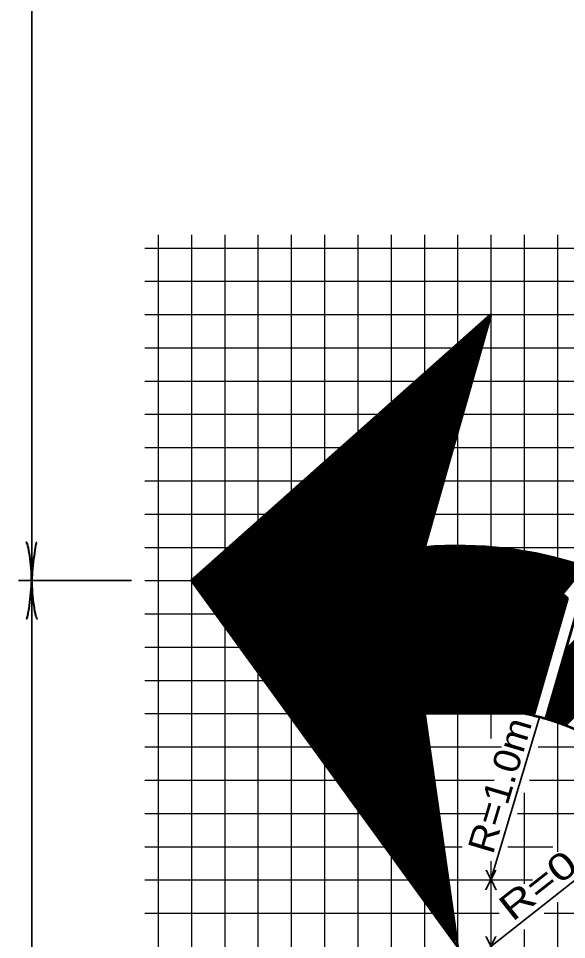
# Model space of a CAD drawing. Extents: x -96 to 617, y -65 to 388.
# Drawn here: x 111.1 to 152.3, y 261.1 to 330.4 of the extents above; entities that cross this region are included whole.
import ezdxf
from ezdxf.enums import TextEntityAlignment as Align

# ---------------------------------------------------------------- set-up
doc = ezdxf.new("R2010")
doc.units = 0
doc.layers.add('1', color=7, linetype='Continuous', lineweight=53)

msp = doc.modelspace()

# ---------------------------------------------------------------- linework, layer by layer
at = {"layer": '1', "lineweight": 25}
for p, q in [((121.579, 314.099), (121.579, 257.099)), ((124.079, 314.099), (124.079, 257.099)), ((126.579, 314.099), (126.579, 257.099)), ((129.079, 314.099), (129.079, 257.099)), ((131.579, 314.099), (131.579, 257.099)), ((134.079, 314.099), (134.079, 257.099)), ((136.579, 314.099), (136.579, 257.099)), ((139.079, 314.099), (139.079, 257.099)), ((141.579, 314.099), (141.579, 257.099)), ((144.079, 314.099), (144.079, 257.099)), ((146.579, 314.099), (146.579, 276.227)), ((149.079, 314.099), (149.079, 278.443)), ((151.579, 314.099), (151.579, 284.164)), ((120.579, 313.099), (182.579, 313.099)), ((120.579, 310.599), (182.579, 310.599)), ((120.579, 308.099), (182.579, 308.099)), ((120.579, 305.599), (154.079, 305.599)), ((120.579, 303.099), (182.579, 303.099)), ((120.579, 300.599), (182.579, 300.599)), ((120.579, 298.099), (182.579, 298.099)), ((120.579, 295.599), (182.579, 295.599)), ((120.579, 293.099), (182.579, 293.099)), ((120.579, 290.599), (141.579, 290.599)), ((142.756, 290.599), (182.579, 290.599)), ((120.579, 288.099), (124.079, 288.099)), ((124.079, 288.099), (152.781, 288.099)), ((120.579, 285.599), (151.995, 285.599)), ((120.579, 283.099), (151.269, 283.099)), ((120.579, 280.599), (150.543, 280.599)), ((151.547, 280.599), (182.579, 280.599)), ((120.579, 278.099), (141.579, 278.099)), ((149.079, 278.099), (149.817, 278.099)), ((150.821, 278.099), (182.579, 278.099)), ((120.579, 275.599), (147.368, 275.599)), ((150.135, 275.599), (182.579, 275.599)), ((120.579, 273.099), (146.831, 273.099)), ((149.469, 273.099), (182.579, 273.099)), ((149.079, 272.153), (149.079, 266.649)), ((120.579, 270.599), (146.16, 270.599)), ((120.579, 268.099), (144.415, 268.099)), ((147.841, 268.099), (151.244, 268.099)), ((146.579, 267.007), (146.579, 257.099)), ((149.079, 266.649), (149.079, 265.306)), ((120.579, 265.599), (146.579, 265.599)), ((146.579, 265.599), (149.695, 265.599)), ((151.579, 263.939), (151.579, 257.099)), ((120.579, 263.099), (147.189, 263.099)), ((150.578, 263.099), (164.079, 263.099)), ((149.079, 261.867), (149.079, 257.099))]:
    msp.add_line(p, q, dxfattribs=at)
at = {"layer": '1'}
for p, q in [((125.155, 286.619), (146.556, 308.02)), ((125.229, 286.516), (146.486, 307.772)), ((125.304, 286.414), (146.415, 307.525)), ((125.081, 286.721), (145.493, 307.134)), ((125.378, 286.312), (146.344, 307.277)), ((125.453, 286.209), (146.273, 307.03)), ((125.527, 286.107), (146.203, 306.782)), ((125.602, 286.005), (146.132, 306.535)), ((125.676, 285.902), (146.061, 306.287)), ((125.75, 285.8), (145.99, 306.04)), ((125.006, 286.823), (143.903, 305.72)), ((125.825, 285.697), (145.92, 305.792)), ((125.899, 285.595), (145.849, 305.545)), ((125.974, 285.493), (145.778, 305.298)), ((126.048, 285.39), (145.708, 305.05)), ((126.123, 285.288), (145.637, 304.803)), ((124.932, 286.926), (142.311, 304.305)), ((126.197, 285.186), (145.566, 304.555)), ((126.271, 285.083), (145.495, 304.308)), ((126.346, 284.981), (145.425, 304.06)), ((126.42, 284.879), (145.354, 303.812)), ((126.495, 284.776), (145.283, 303.565)), ((126.569, 284.674), (145.213, 303.318)), ((124.857, 287.028), (140.72, 302.891)), ((126.644, 284.572), (145.142, 303.07)), ((126.718, 284.469), (145.071, 302.823)), ((126.792, 284.367), (145.001, 302.575)), ((126.867, 284.265), (144.93, 302.328)), ((126.941, 284.162), (144.859, 302.08)), ((124.783, 287.13), (139.13, 301.477)), ((127.016, 284.06), (144.788, 301.833)), ((127.09, 283.958), (144.718, 301.585)), ((127.165, 283.855), (144.647, 301.338)), ((127.239, 283.753), (144.576, 301.09)), ((127.313, 283.651), (144.506, 300.843)), ((127.388, 283.548), (144.435, 300.595)), ((124.708, 287.233), (137.538, 300.063)), ((127.462, 283.446), (144.364, 300.348)), ((127.537, 283.344), (144.293, 300.1)), ((127.611, 283.241), (144.223, 299.853)), ((127.686, 283.139), (144.152, 299.605)), ((127.76, 283.037), (144.081, 299.358)), ((124.634, 287.335), (135.947, 298.649)), ((127.834, 282.934), (144.011, 299.11)), ((127.909, 282.832), (143.94, 298.863)), ((127.983, 282.729), (143.869, 298.615)), ((128.058, 282.627), (143.798, 298.368)), ((128.132, 282.525), (143.728, 298.12)), ((128.207, 282.423), (143.657, 297.873)), ((124.559, 287.437), (134.356, 297.234)), ((128.281, 282.32), (143.586, 297.625)), ((128.356, 282.218), (143.516, 297.378)), ((128.43, 282.115), (143.445, 297.13)), ((128.504, 282.013), (143.374, 296.883)), ((128.579, 281.911), (143.303, 296.635)), ((128.653, 281.808), (143.233, 296.388)), ((124.485, 287.54), (132.766, 295.82)), ((128.728, 281.706), (143.162, 296.14)), ((128.802, 281.604), (143.091, 295.893)), ((128.877, 281.501), (143.021, 295.645)), ((128.951, 281.399), (142.95, 295.398)), ((129.025, 281.297), (142.879, 295.15)), ((124.411, 287.642), (131.174, 294.406)), ((129.1, 281.194), (142.809, 294.903)), ((129.174, 281.092), (142.738, 294.656)), ((129.249, 280.99), (142.667, 294.408)), ((129.323, 280.887), (142.596, 294.161)), ((129.398, 280.785), (142.526, 293.913)), ((129.472, 280.683), (142.455, 293.666)), ((124.336, 287.744), (129.584, 292.992)), ((129.547, 280.58), (142.384, 293.418)), ((129.621, 280.478), (142.314, 293.171)), ((129.695, 280.376), (142.243, 292.923)), ((129.77, 280.273), (142.172, 292.676)), ((129.844, 280.171), (142.101, 292.428)), ((124.262, 287.847), (127.993, 291.577)), ((129.919, 280.069), (142.031, 292.181)), ((129.993, 279.966), (141.96, 291.933)), ((130.067, 279.864), (141.889, 291.686)), ((130.142, 279.762), (141.819, 291.438)), ((130.216, 279.659), (141.748, 291.191)), ((130.291, 279.557), (141.677, 290.943)), ((124.187, 287.949), (126.402, 290.163)), ((130.365, 279.454), (141.606, 290.696)), ((130.44, 279.352), (141.695, 290.607)), ((130.514, 279.25), (141.886, 290.621)), ((130.588, 279.147), (142.076, 290.635)), ((130.663, 279.045), (142.265, 290.647)), ((130.737, 278.943), (142.452, 290.657)), ((130.812, 278.84), (142.639, 290.668)), ((130.886, 278.738), (142.824, 290.675)), ((130.961, 278.636), (143.007, 290.682)), ((131.035, 278.533), (143.191, 290.689)), ((131.11, 278.431), (143.372, 290.693)), ((131.184, 278.329), (143.552, 290.697)), ((131.258, 278.226), (143.732, 290.7)), ((131.333, 278.124), (143.91, 290.701)), ((131.407, 278.022), (144.087, 290.701)), ((131.482, 277.919), (144.264, 290.702)), ((131.556, 277.817), (144.439, 290.7)), ((131.631, 277.715), (144.613, 290.697)), ((131.705, 277.612), (144.786, 290.694)), ((131.779, 277.51), (144.959, 290.689)), ((131.854, 277.408), (145.129, 290.683)), ((131.928, 277.305), (145.3, 290.677)), ((132.003, 277.203), (145.47, 290.67)), ((132.077, 277.101), (145.638, 290.661)), ((132.152, 276.998), (145.805, 290.652)), ((132.226, 276.896), (145.973, 290.643)), ((132.3, 276.793), (146.138, 290.631)), ((132.375, 276.691), (146.303, 290.619)), ((132.449, 276.589), (146.468, 290.607)), ((132.524, 276.486), (146.631, 290.593)), ((132.598, 276.384), (146.793, 290.579)), ((132.673, 276.282), (146.955, 290.564)), ((132.747, 276.18), (147.116, 290.549)), ((132.821, 276.077), (147.276, 290.531)), ((132.896, 275.975), (147.435, 290.514)), ((132.97, 275.872), (147.594, 290.497)), ((133.045, 275.77), (147.751, 290.477)), ((133.119, 275.668), (147.908, 290.457)), ((133.194, 275.565), (148.065, 290.437)), ((133.268, 275.463), (148.221, 290.416)), ((133.343, 275.361), (148.375, 290.393)), ((133.417, 275.258), (148.529, 290.371)), ((133.491, 275.156), (148.684, 290.348)), ((133.566, 275.054), (148.836, 290.323)), ((133.64, 274.951), (148.987, 290.299)), ((133.715, 274.849), (149.139, 290.274)), ((133.789, 274.747), (149.29, 290.248)), ((133.863, 274.644), (149.44, 290.22)), ((133.938, 274.542), (149.589, 290.193)), ((134.012, 274.44), (149.738, 290.166)), ((134.087, 274.337), (149.886, 290.136)), ((134.161, 274.235), (150.033, 290.107)), ((134.236, 274.133), (150.18, 290.077)), ((134.31, 274.03), (150.327, 290.047)), ((134.385, 273.928), (150.472, 290.015)), ((134.459, 273.826), (150.617, 289.983)), ((134.533, 273.723), (150.761, 289.951)), ((134.608, 273.621), (150.905, 289.918)), ((134.682, 273.519), (151.048, 289.884)), ((134.757, 273.416), (151.19, 289.85)), ((134.831, 273.314), (151.333, 289.815)), ((134.906, 273.212), (151.474, 289.78)), ((134.98, 273.109), (151.614, 289.743)), ((135.054, 273.007), (151.754, 289.707)), ((135.129, 272.904), (151.895, 289.67)), ((135.203, 272.802), (152.033, 289.632)), ((135.278, 272.7), (152.171, 289.593)), ((135.352, 272.597), (152.309, 289.555)), ((135.427, 272.495), (152.448, 289.516)), ((135.501, 272.393), (152.584, 289.475)), ((135.576, 272.29), (152.72, 289.435)), ((124.113, 288.051), (124.811, 288.749)), ((135.65, 272.188), (152.856, 289.394)), ((141.737, 278.099), (152.992, 289.353)), ((141.914, 278.099), (153.126, 289.31)), ((142.091, 278.099), (153.26, 289.267)), ((142.267, 278.099), (153.394, 289.225)), ((142.444, 278.099), (153.527, 289.181)), ((142.621, 278.099), (153.535, 289.013)), ((142.798, 278.099), (152.701, 288.002)), ((151.717, 281.184), (157.883, 287.35)), ((151.789, 281.433), (157.766, 287.41)), ((151.861, 281.682), (157.649, 287.47)), ((151.934, 281.931), (157.531, 287.529)), ((152.006, 282.18), (157.413, 287.587)), ((152.078, 282.429), (157.295, 287.646)), ((152.151, 282.678), (157.176, 287.704)), ((152.223, 282.928), (157.056, 287.761)), ((142.975, 278.099), (151.961, 287.085)), ((143.151, 278.099), (152.058, 287.005)), ((143.328, 278.099), (152.155, 286.925)), ((143.505, 278.099), (152.252, 286.845)), ((143.682, 278.099), (152.328, 286.745)), ((152.337, 286.775), (149.774, 277.949)), ((150.921, 278.443), (159.141, 286.663)), ((150.993, 278.693), (159.028, 286.727)), ((151.066, 278.942), (158.915, 286.791)), ((151.138, 279.191), (158.802, 286.855)), ((151.21, 279.44), (158.689, 286.919)), ((151.283, 279.689), (158.575, 286.982)), ((151.355, 279.938), (158.461, 287.044)), ((151.427, 280.187), (158.346, 287.106)), ((151.5, 280.436), (158.231, 287.168)), ((151.572, 280.685), (158.116, 287.229)), ((151.644, 280.935), (157.999, 287.29)), ((143.858, 278.099), (152.256, 286.496)), ((144.035, 278.099), (152.184, 286.247)), ((144.212, 278.099), (152.111, 285.998)), ((150.711, 277.703), (159.475, 286.467)), ((150.776, 277.945), (159.363, 286.532)), ((150.847, 277.663), (159.586, 286.401)), ((150.849, 278.194), (159.252, 286.598)), ((150.983, 277.622), (159.696, 286.334)), ((151.118, 277.58), (159.805, 286.267)), ((151.251, 277.536), (159.915, 286.2)), ((151.385, 277.493), (160.024, 286.132)), ((151.517, 277.449), (160.133, 286.064)), ((151.648, 277.403), (160.24, 285.995)), ((144.389, 278.099), (152.039, 285.749)), ((144.566, 278.099), (151.967, 285.5)), ((151.779, 277.357), (160.348, 285.926)), ((151.909, 277.311), (160.456, 285.857)), ((152.038, 277.262), (160.563, 285.788)), ((152.166, 277.214), (160.669, 285.717)), ((144.742, 278.099), (151.894, 285.25)), ((144.919, 278.099), (151.822, 285.001)), ((145.096, 278.099), (151.75, 284.752)), ((145.273, 278.099), (151.677, 284.503)), ((145.45, 278.099), (151.605, 284.254)), ((145.626, 278.099), (151.533, 284.005)), ((145.803, 278.099), (151.46, 283.756)), ((145.98, 278.099), (151.388, 283.507)), ((146.157, 278.099), (151.315, 283.257)), ((146.333, 278.099), (151.243, 283.008)), ((146.51, 278.099), (151.171, 282.759)), ((146.687, 278.099), (151.099, 282.51)), ((146.864, 278.099), (151.026, 282.261)), ((147.04, 278.099), (150.954, 282.012)), ((147.217, 278.099), (150.881, 281.763)), ((147.394, 278.099), (150.809, 281.514)), ((147.571, 278.099), (150.737, 281.264)), ((147.748, 278.099), (150.664, 281.015)), ((147.924, 278.099), (150.592, 280.766)), ((148.101, 278.099), (150.52, 280.517)), ((148.278, 278.099), (150.447, 280.268)), ((148.455, 278.099), (150.375, 280.019)), ((148.631, 278.099), (150.303, 279.77)), ((148.808, 278.099), (150.23, 279.521)), ((148.985, 278.099), (150.158, 279.272)), ((149.148, 278.084), (150.086, 279.022)), ((149.295, 278.055), (150.013, 278.773)), ((149.44, 278.024), (149.941, 278.524)), ((135.724, 272.086), (141.599, 277.96)), ((135.799, 271.983), (141.621, 277.805)), ((135.873, 271.881), (141.643, 277.65)), ((149.585, 277.991), (149.869, 278.275)), ((149.73, 277.959), (149.796, 278.026)), ((150.155, 277.855), (150.156, 277.855)), ((150.573, 277.742), (150.574, 277.743)), ((135.948, 271.779), (141.665, 277.496)), ((136.022, 271.676), (141.687, 277.341)), ((136.096, 271.574), (141.709, 277.186)), ((136.171, 271.472), (141.731, 277.032)), ((136.245, 271.369), (141.753, 276.877)), ((136.32, 271.267), (141.775, 276.722)), ((136.394, 271.165), (141.797, 276.568)), ((136.469, 271.062), (141.819, 276.413)), ((136.543, 270.96), (141.842, 276.258)), ((136.618, 270.858), (141.864, 276.104)), ((136.692, 270.755), (141.886, 275.949)), ((136.766, 270.653), (141.908, 275.794)), ((136.841, 270.55), (141.93, 275.64)), ((136.915, 270.448), (141.952, 275.485)), ((136.99, 270.346), (141.974, 275.33)), ((137.064, 270.243), (141.996, 275.176)), ((137.139, 270.141), (142.018, 275.021)), ((137.213, 270.039), (142.04, 274.866)), ((137.287, 269.936), (142.062, 274.712)), ((137.362, 269.834), (142.085, 274.557)), ((137.436, 269.732), (142.107, 274.402)), ((137.511, 269.629), (142.129, 274.248)), ((137.585, 269.527), (142.151, 274.093)), ((137.66, 269.425), (142.173, 273.938)), ((137.734, 269.322), (142.195, 273.784)), ((137.808, 269.22), (142.217, 273.629)), ((137.883, 269.118), (142.239, 273.474)), ((137.957, 269.015), (142.261, 273.319)), ((138.032, 268.913), (142.284, 273.165)), ((138.106, 268.811), (142.306, 273.01)), ((138.181, 268.708), (142.328, 272.855)), ((138.255, 268.606), (142.35, 272.701)), ((138.329, 268.504), (142.372, 272.546)), ((138.404, 268.401), (142.394, 272.391)), ((138.478, 268.299), (142.416, 272.237)), ((138.553, 268.197), (142.438, 272.082)), ((138.627, 268.094), (142.46, 271.927)), ((138.702, 267.992), (142.482, 271.773)), ((138.776, 267.89), (142.504, 271.618)), ((138.85, 267.787), (142.527, 271.463)), ((138.925, 267.685), (142.549, 271.309)), ((138.999, 267.582), (142.571, 271.154)), ((139.074, 267.48), (142.593, 270.999)), ((139.148, 267.378), (142.615, 270.845)), ((139.223, 267.275), (142.637, 270.69)), ((139.297, 267.173), (142.659, 270.535)), ((139.371, 267.071), (142.681, 270.38)), ((139.446, 266.969), (142.703, 270.226)), ((139.52, 266.866), (142.725, 270.071)), ((139.595, 266.764), (142.748, 269.916)), ((139.669, 266.661), (142.77, 269.762)), ((139.744, 266.559), (142.792, 269.607)), ((139.818, 266.457), (142.814, 269.452)), ((139.893, 266.354), (142.836, 269.298)), ((139.967, 266.252), (142.858, 269.143)), ((140.041, 266.15), (142.88, 268.988)), ((140.116, 266.047), (142.902, 268.834)), ((140.19, 265.945), (142.924, 268.679)), ((140.265, 265.843), (142.946, 268.524)), ((140.339, 265.74), (142.969, 268.37)), ((140.414, 265.638), (142.991, 268.215)), ((140.488, 265.536), (143.013, 268.06)), ((140.562, 265.433), (143.035, 267.906)), ((140.637, 265.331), (143.057, 267.751)), ((140.711, 265.229), (143.079, 267.596)), ((140.786, 265.126), (143.101, 267.442)), ((140.86, 265.024), (143.123, 267.287)), ((140.935, 264.922), (143.145, 267.132)), ((141.009, 264.819), (143.167, 266.978)), ((141.083, 264.717), (143.189, 266.823)), ((141.158, 264.615), (143.212, 266.668)), ((141.232, 264.512), (143.234, 266.513)), ((141.307, 264.41), (143.256, 266.359)), ((141.381, 264.308), (143.278, 266.204)), ((141.456, 264.205), (143.3, 266.049)), ((141.53, 264.103), (143.322, 265.895)), ((141.605, 264), (143.344, 265.74)), ((141.679, 263.898), (143.366, 265.585)), ((141.753, 263.796), (143.388, 265.431)), ((141.828, 263.693), (143.41, 265.276)), ((141.902, 263.591), (143.433, 265.121)), ((141.977, 263.489), (143.455, 264.967)), ((142.051, 263.386), (143.477, 264.812)), ((142.125, 263.284), (143.499, 264.657)), ((142.2, 263.182), (143.521, 264.503)), ((142.274, 263.079), (143.543, 264.348)), ((142.349, 262.977), (143.565, 264.193)), ((142.423, 262.875), (143.587, 264.039)), ((142.498, 262.772), (143.609, 263.884)), ((142.572, 262.67), (143.631, 263.729)), ((142.647, 262.568), (143.654, 263.575)), ((142.721, 262.465), (143.676, 263.42)), ((142.795, 262.363), (143.698, 263.265)), ((142.87, 262.261), (143.72, 263.111)), ((142.944, 262.158), (143.742, 262.956)), ((143.019, 262.056), (143.764, 262.801)), ((143.093, 261.954), (143.786, 262.647)), ((143.168, 261.851), (143.808, 262.492)), ((143.242, 261.749), (143.83, 262.337)), ((143.316, 261.647), (143.852, 262.183)), ((143.391, 261.544), (143.874, 262.028)), ((143.465, 261.442), (143.897, 261.873)), ((143.54, 261.339), (143.919, 261.719)), ((143.614, 261.237), (143.941, 261.564)), ((143.689, 261.135), (143.963, 261.409)), ((143.763, 261.032), (143.985, 261.254))]:
    msp.add_line(p, q, dxfattribs=at)
at = {"layer": '1', "lineweight": 35}
for p, q in [((119.579, 288.099), (111.079, 288.099)), ((150.229, 277.837), (146.579, 265.599)), ((160.156, 271.312), (146.579, 260.599))]:
    msp.add_line(p, q, dxfattribs=at)
msp.add_lwpolyline([(112.079, 345.599), (112.079, 288.099), (112.079, 245.599)], dxfattribs=at)
at = {"layer": '1'}
for points in [[(149.079, 278.099), (141.579, 278.099), (144.079, 260.599), (124.079, 288.099), (146.579, 308.099), (141.579, 290.599)], [(150.707, 277.705), (153.264, 286.512), (153.763, 286.535), (153.643, 289.143), (151.951, 287.093), (152.337, 286.775)]]:
    msp.add_lwpolyline(points, dxfattribs=at)
at = {"layer": '1', "lineweight": 25}
for points in [[(151.579, 280.708), (151.579, 275.108), (151.579, 267.723)], [(148.581, 270.599), (152.737, 270.599), (182.579, 270.599)]]:
    msp.add_lwpolyline(points, dxfattribs=at)
at = {"layer": '1'}
for centre, radius, start, end in [((144.08, 260.602), 30.101, 71.47601, 94.76641), ((145.536, 259.884), 18.556, 76.79864, 78.99479), ((145.53, 259.863), 18.578, 73.81998, 76.79324), ((145.53, 259.863), 18.578, 73.81998, 76.79324), ((145.536, 259.884), 18.556, 2.2078, 73.82193)]:
    msp.add_arc(centre, radius, start, end, dxfattribs=at)
at = {"layer": '1', "lineweight": 40}
for centre, major_axis, ratio, start_param, end_param in [((111.802, 289.19), (0.156, -1.786), 0.122415, 0.896353, 3.141593), ((111.802, 289.19), (0.156, -1.786), 0.122415, 0.896353, 3.141593), ((112.29, 289.219), (-0.176, -1.756), 0.07063, 3.140715, 5.41811), ((112.29, 289.219), (-0.176, -1.756), 0.07063, 3.140715, 5.41811), ((111.867, 286.978), (0.176, 1.756), 0.07063, 3.140715, 5.41811), ((111.867, 286.978), (0.176, 1.756), 0.07063, 3.140715, 5.41811), ((112.355, 287.007), (-0.156, 1.786), 0.122415, 0.896353, 3.141593), ((112.355, 287.007), (-0.156, 1.786), 0.122415, 0.896353, 3.141593)]:
    msp.add_ellipse(centre, major_axis=major_axis, ratio=ratio, start_param=start_param, end_param=end_param, dxfattribs=at)

# ---------------------------------------------------------------- texts
at = {"layer": '1'}
for s, rotation, width, p in [('R=1.0m', 73.39, 1.1, (148.207, 272.425)), ('R=0.7m', 38.276, 1.3, (153.01, 266.205))]:
    msp.add_text(s, height=2, rotation=rotation, dxfattribs=dict(at, width=width)).set_placement(p, align=Align.CENTER)
at = {"layer": '1', "width": 0.75}
for p in [(146.579, 264.849), (146.579, 259.849)]:
    msp.add_text('X', height=1.5, dxfattribs=at).set_placement(p, align=Align.CENTER)

doc.saveas('drawing.dxf')
